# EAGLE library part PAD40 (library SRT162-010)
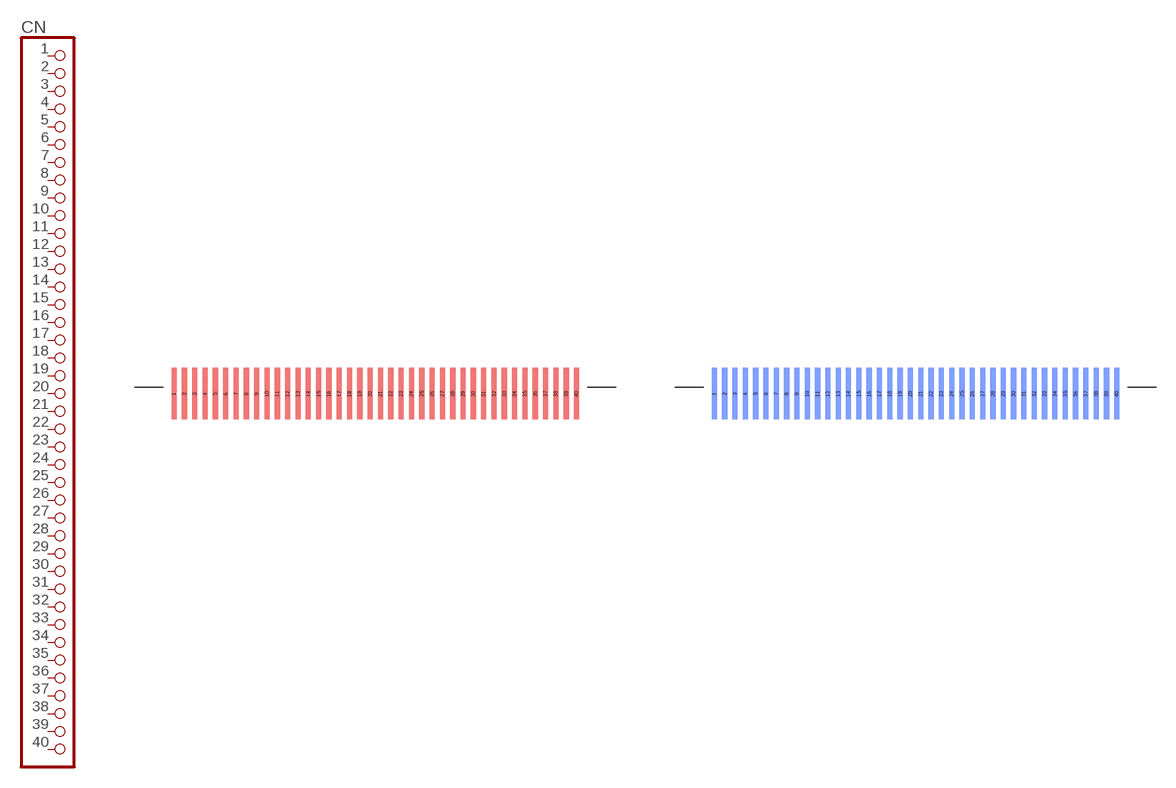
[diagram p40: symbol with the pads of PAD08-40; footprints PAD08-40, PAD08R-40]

Designator prefix CN

## PAD4008  [PAD08-40]
1  1  pas
2  2  pas
3  3  pas
4  4  pas
5  5  pas
6  6  pas
7  7  pas
8  8  pas
9  9  pas
10  10  pas
11  11  pas
12  12  pas
13  13  pas
14  14  pas
15  15  pas
16  16  pas
17  17  pas
18  18  pas
19  19  pas
20  20  pas
21  21  pas
22  22  pas
23  23  pas
24  24  pas
25  25  pas
26  26  pas
27  27  pas
28  28  pas
29  29  pas
30  30  pas
31  31  pas
32  32  pas
33  33  pas
34  34  pas
35  35  pas
36  36  pas
37  37  pas
38  38  pas
39  39  pas
40  40  pas

## PAD4008R  [PAD08R-40]
Pads as for PAD08-40

## PAD40Z  [PAD08-40Z]
Pads as for PAD08-40

## Footprint PAD08-40 (pad centres in mm)
smd 0.4 x 4: 1 -15.2,0; 2 -14.4,0; 3 -13.6,0; 4 -12.8,0; 5 -12,0; 6 -11.2,0; 7 -10.4,0; 8 -9.6,0; 9 -8.8,0; 10 -8,0; 11 -7.2,0; 12 -6.4,0; 13 -5.6,0; 14 -4.8,0; 15 -4,0; 16 -3.2,0; 17 -2.4,0; 18 -1.6,0; 19 -0.8,0; 20 0,0; 21 0.8,0; 22 1.6,0; 23 2.4,0; 24 3.2,0; 25 4,0; 26 4.8,0; 27 5.6,0; 28 6.4,0; 29 7.2,0; 30 8,0; 31 8.8,0; 32 9.6,0; 33 10.4,0; 34 11.2,0; 35 12,0; 36 12.8,0; 37 13.6,0; 38 14.4,0; 39 15.2,0; 40 16,0

## Footprint PAD08R-40 (pad centres in mm)
smd 0.4 x 4 bottom: 1 -15.2,0; 2 -14.4,0; 3 -13.6,0; 4 -12.8,0; 5 -12,0; 6 -11.2,0; 7 -10.4,0; 8 -9.6,0; 9 -8.8,0; 10 -8,0; 11 -7.2,0; 12 -6.4,0; 13 -5.6,0; 14 -4.8,0; 15 -4,0; 16 -3.2,0; 17 -2.4,0; 18 -1.6,0; 19 -0.8,0; 20 0,0; 21 0.8,0; 22 1.6,0; 23 2.4,0; 24 3.2,0; 25 4,0; 26 4.8,0; 27 5.6,0; 28 6.4,0; 29 7.2,0; 30 8,0; 31 8.8,0; 32 9.6,0; 33 10.4,0; 34 11.2,0; 35 12,0; 36 12.8,0; 37 13.6,0; 38 14.4,0; 39 15.2,0; 40 16,0

## Footprint PAD08-40Z (pad centres in mm)
smd 0.5 x 2: 1 -15.2,1; 2 -14.4,-1; 3 -13.6,1; 4 -12.8,-1; 5 -12,1; 6 -11.2,-1; 7 -10.4,1; 8 -9.6,-1; 9 -8.8,1; 10 -8,-1; 11 -7.2,1; 12 -6.4,-1; 13 -5.6,1; 14 -4.8,-1; 15 -4,1; 16 -3.2,-1; 17 -2.4,1; 18 -1.6,-1; 19 -0.8,1; 20 0,-1; 21 0.8,1; 22 1.6,-1; 23 2.4,1; 24 3.2,-1; 25 4,1; 26 4.8,-1; 27 5.6,1; 28 6.4,-1; 29 7.2,1; 30 8,-1; 31 8.8,1; 32 9.6,-1; 33 10.4,1; 34 11.2,-1; 35 12,1; 36 12.8,-1; 37 13.6,1; 38 14.4,-1; 39 15.2,1; 40 16,-1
